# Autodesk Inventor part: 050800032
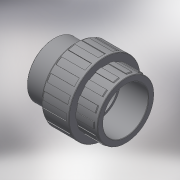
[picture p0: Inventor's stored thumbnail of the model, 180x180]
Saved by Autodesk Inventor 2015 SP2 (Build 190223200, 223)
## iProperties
Created: 2017-10
Part Number: 050800032
Material: Generic
Description: PLASSON UNION+O RING-CEM PVC 32
Document SubType Name: Modeling
Designer: Кирилл
Density: 1 g/cm^3
Appearance: Default
Author: Кирилл
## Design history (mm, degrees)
derived "050800.ipt"
feature "Solid1::050800.ipt"
tag "TaggingFeature1"
body "Solid1"
other parameters: "d0" = 58, "d3" = 32, "d4" = 32, "d5" = 38.4, "d7" = 40.96, "d8" = 59, "d9" = 22, "d10" = 22, "d11" = 28.8, "d12" = 30.4, "d14" = 16.5, "d15" = 16.5, "d16" = 12.6, "d17" = 2.2, "d19" = 57.82, "d20" = 2.2, "d21" = 1.77, "d25" = 5.9, "d26" = 2.95, "d27" = 20.52, "d28" = 0, "d32" = 5.9, "d33" = 2.95, "d35" = 0, "d39" = 0.32, "d45" = 0.48, "d49" = 360 deg, "d51" = 0.59, "d55" = 360 deg, "d_" = 32, "E_" = 59, "H_" = 58, "l_" = 22, "l_1" = 22, "Z_" = 13, "d13" = 14, "d24" = 22.8, "d40" = 0.48, "d44" = 0.59
